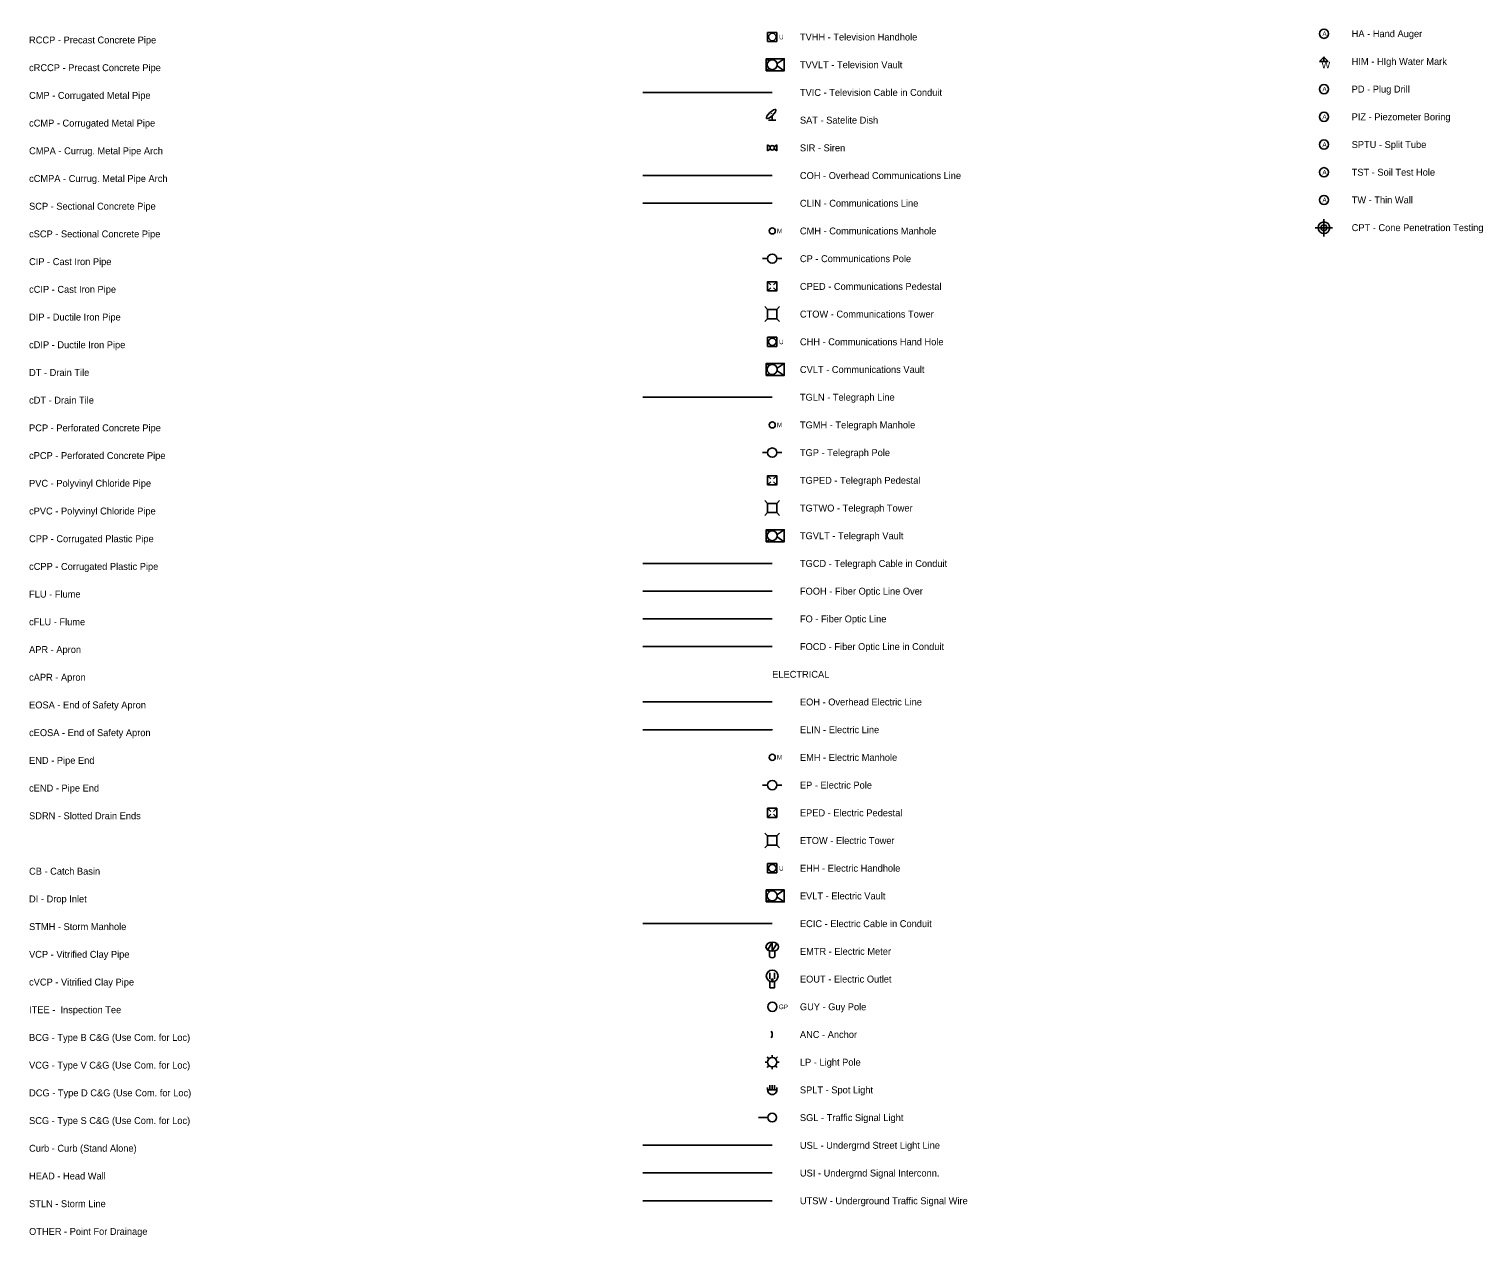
# Model space of a CAD drawing. Extents: x 2147712 to 2176316, y 2125036 to 2131746.
# Drawn here: x 2165470 to 2167044, y 2127374 to 2128682 of the extents above; entities that cross this region are included whole.
import ezdxf

# ---------------------------------------------------------------- set-up
doc = ezdxf.new("R2010")
doc.units = 0
for name, color, linetype in [('COMM LIN INP', 7, 'Continuous'), ('COMM PT INP', 7, 'Continuous'), ('Default', 7, 'Continuous'), ('MANMD STRU INP', 7, 'Continuous'), ('PWR LIN INP', 7, 'Continuous'), ('PWR LIN OVHD INP', 7, 'Continuous'), ('PWR PT INP', 7, 'Continuous')]:
    doc.layers.add(name, color=color, linetype=linetype)

msp = doc.modelspace()

# ---------------------------------------------------------------- linework, layer by layer
at = {"layer": 'COMM LIN INP'}
for p, q in [((2166134.5, 2128613.1), (2166274.5, 2128613.1)), ((2166134.5, 2128523.1), (2166274.5, 2128523.1)), ((2166134.5, 2128493.1), (2166274.5, 2128493.1)), ((2166134.5, 2128283.1), (2166274.5, 2128283.1)), ((2166134.5, 2128103.1), (2166274.5, 2128103.1)), ((2166134.5, 2128073.1), (2166274.5, 2128073.1)), ((2166134.5, 2128043.1), (2166274.5, 2128043.1)), ((2166134.5, 2128013.1), (2166274.5, 2128013.1))]:
    msp.add_line(p, q, dxfattribs=at)
at = {"layer": 'COMM PT INP'}
for p, q in [((2166274.5, 2128673.1), (2166274.5, 2128673.1)), ((2166268, 2128649.6), (2166271.3, 2128647.4)), ((2166287.5, 2128649.6), (2166279.7, 2128644.4)), ((2166271.3, 2128638.8), (2166268, 2128636.6)), ((2166279.7, 2128641.8), (2166287.5, 2128636.6)), ((2166270.6, 2128583.1), (2166278.4, 2128583.1)), ((2166273.9, 2128590), (2166273.3, 2128590.6)), ((2166274.5, 2128583.1), (2166274.5, 2128587.9)), ((2166269.5, 2128556.3), (2166269.5, 2128549.9)), ((2166272.5, 2128554.2), (2166269.5, 2128556.3)), ((2166272.5, 2128552), (2166269.5, 2128549.9)), ((2166276.5, 2128554.2), (2166279.5, 2128556.3)), ((2166276.5, 2128552), (2166279.5, 2128549.9)), ((2166279.5, 2128556.3), (2166279.5, 2128549.9)), ((2166269.5, 2128433.1), (2166263.9, 2128433.1)), ((2166279.5, 2128433.1), (2166285.1, 2128433.1)), ((2166269.5, 2128408.1), (2166273, 2128404.6)), ((2166276, 2128404.6), (2166279.5, 2128408.1)), ((2166269.5, 2128398.1), (2166273, 2128401.6)), ((2166274.5, 2128403.1), (2166274.5, 2128403.1)), ((2166276, 2128401.6), (2166279.5, 2128398.1)), ((2166266.5, 2128381.1), (2166269.5, 2128378.1)), ((2166282.5, 2128381.1), (2166279.5, 2128378.1)), ((2166269.5, 2128368.1), (2166266.5, 2128365.1)), ((2166274.5, 2128373.1), (2166274.5, 2128373.1)), ((2166279.5, 2128368.1), (2166282.5, 2128365.1)), ((2166274.5, 2128343.1), (2166274.5, 2128343.1)), ((2166268, 2128319.6), (2166271.3, 2128317.4)), ((2166287.5, 2128319.6), (2166279.7, 2128314.4)), ((2166271.3, 2128308.8), (2166268, 2128306.6)), ((2166279.7, 2128311.8), (2166287.5, 2128306.6)), ((2166269.5, 2128223.1), (2166263.9, 2128223.1)), ((2166279.5, 2128223.1), (2166285.1, 2128223.1)), ((2166269.5, 2128198.1), (2166273, 2128194.6)), ((2166269.5, 2128188.1), (2166273, 2128191.6)), ((2166274.5, 2128193.1), (2166274.5, 2128193.1)), ((2166276, 2128194.6), (2166279.5, 2128198.1)), ((2166276, 2128191.6), (2166279.5, 2128188.1)), ((2166266.5, 2128171.1), (2166269.5, 2128168.1)), ((2166269.5, 2128158.1), (2166266.5, 2128155.1)), ((2166274.5, 2128163.1), (2166274.5, 2128163.1)), ((2166282.5, 2128171.1), (2166279.5, 2128168.1)), ((2166279.5, 2128158.1), (2166282.5, 2128155.1)), ((2166268, 2128139.6), (2166271.3, 2128137.4)), ((2166271.3, 2128128.8), (2166268, 2128126.6)), ((2166287.5, 2128139.6), (2166279.7, 2128134.4)), ((2166279.7, 2128131.8), (2166287.5, 2128126.6))]:
    msp.add_line(p, q, dxfattribs=at)
for points in [[(2166269.5, 2128678.1), (2166279.5, 2128678.1)], [(2166269.5, 2128678.1), (2166269.5, 2128668.1)], [(2166279.5, 2128678.1), (2166279.5, 2128668.1)], [(2166269.5, 2128668.1), (2166279.5, 2128668.1)], [(2166269.5, 2128348.1), (2166279.5, 2128348.1)], [(2166269.5, 2128348.1), (2166269.5, 2128338.1)], [(2166279.5, 2128348.1), (2166279.5, 2128338.1)], [(2166269.5, 2128338.1), (2166279.5, 2128338.1)]]:
    msp.add_lwpolyline(points, dxfattribs=at)
for points in [[(2166268, 2128636.6), (2166287.5, 2128636.6), (2166287.5, 2128649.6), (2166268, 2128649.6)], [(2166269.5, 2128398.1), (2166279.5, 2128398.1), (2166279.5, 2128408.1), (2166269.5, 2128408.1)], [(2166269.5, 2128368.1), (2166279.5, 2128368.1), (2166279.5, 2128378.1), (2166269.5, 2128378.1)], [(2166268, 2128306.6), (2166287.5, 2128306.6), (2166287.5, 2128319.6), (2166268, 2128319.6)], [(2166269.5, 2128188.1), (2166279.5, 2128188.1), (2166279.5, 2128198.1), (2166269.5, 2128198.1)], [(2166269.5, 2128158.1), (2166279.5, 2128158.1), (2166279.5, 2128168.1), (2166269.5, 2128168.1)], [(2166268, 2128126.6), (2166287.5, 2128126.6), (2166287.5, 2128139.6), (2166268, 2128139.6)]]:
    msp.add_lwpolyline(points, close=True, dxfattribs=at)
for centre, radius in [((2166274.6, 2128673.1), 4.01), ((2166274.5, 2128643.1), 5.4), ((2166274.5, 2128553.1), 2.38), ((2166274.5, 2128463.1), 3.31), ((2166274.5, 2128433.1), 5), ((2166274.6, 2128343.1), 4.01), ((2166274.5, 2128313.1), 5.4), ((2166274.5, 2128253.1), 3.31), ((2166274.5, 2128223.1), 5), ((2166274.5, 2128133.1), 5.4)]:
    msp.add_circle(centre, radius, dxfattribs=at)
msp.add_ellipse((2166273.4, 2128589.7), major_axis=(-4.99, -4.74), ratio=0.30554, dxfattribs=at)
at = {"layer": 'Default'}
for p, q in [((2166871.9, 2128651.3), (2166876.6, 2128646.6)), ((2166871.9, 2128646.6), (2166876.6, 2128646.6)), ((2166871.9, 2128466.6), (2166871.9, 2128476)), ((2166871.9, 2128472.8), (2166871.9, 2128469.7)), ((2166871.9, 2128466.6), (2166862.5, 2128466.6)), ((2166868.8, 2128466.6), (2166865.7, 2128466.6)), ((2166871.9, 2128466.6), (2166871.9, 2128457.2)), ((2166871.9, 2128466.6), (2166881.3, 2128466.6)), ((2166871.9, 2128460.4), (2166871.9, 2128463.5)), ((2166875, 2128466.6), (2166878.1, 2128466.6))]:
    msp.add_line(p, q, dxfattribs=at)
msp.add_lwpolyline([(2166867.2, 2128646.6), (2166871.9, 2128651.3), (2166871.9, 2128646.6)], close=True, dxfattribs=at)
for points in [[(2166868.8, 2128466.6), (2166871.9, 2128466.6), (2166871.9, 2128469.7)], [(2166875, 2128466.6), (2166871.9, 2128466.6), (2166871.9, 2128463.5)]]:
    msp.add_lwpolyline(points, dxfattribs=at)
for centre, radius in [((2166871.9, 2128676.6), 5), ((2166871.9, 2128616.6), 5), ((2166871.9, 2128586.6), 5), ((2166871.9, 2128556.6), 5), ((2166871.9, 2128526.6), 5), ((2166871.9, 2128496.6), 5), ((2166871.9, 2128466.6), 6.25)]:
    msp.add_circle(centre, radius, dxfattribs=at)
for radius, start, end in [(6.25, 0, 90), (6.25, 180, 270), (3.12, 90, 180), (3.12, 180, 270), (3.12, 0, 90), (3.12, 270, 360)]:
    msp.add_arc((2166871.9, 2128466.6), radius, start, end, dxfattribs=at)
at = {"layer": 'MANMD STRU INP'}
msp.add_line((2166269.7, 2127503.1), (2166259.5, 2127503.1), dxfattribs=at)
msp.add_circle((2166274.5, 2127503.1), 4.76, dxfattribs=at)
at = {"layer": 'PWR LIN INP'}
for p, q in [((2166134.5, 2127923.1), (2166274.5, 2127923.1)), ((2166134.5, 2127713.1), (2166274.5, 2127713.1)), ((2166134.5, 2127473.1), (2166274.5, 2127473.1)), ((2166134.5, 2127443.1), (2166274.5, 2127443.1)), ((2166134.5, 2127413.1), (2166274.5, 2127413.1))]:
    msp.add_line(p, q, dxfattribs=at)
at = {"layer": 'PWR LIN OVHD INP'}
msp.add_line((2166274.5, 2127953.1), (2166134.5, 2127953.1), dxfattribs=at)
at = {"layer": 'PWR PT INP'}
for p, q in [((2166274.4, 2127922.9), (2166274.6, 2127923.3)), ((2166274.4, 2127923.3), (2166274.6, 2127922.9)), ((2166269.5, 2127863.1), (2166263.9, 2127863.1)), ((2166279.5, 2127863.1), (2166285.1, 2127863.1)), ((2166269.5, 2127838.1), (2166273, 2127834.6)), ((2166269.5, 2127828.1), (2166273, 2127831.6)), ((2166274.5, 2127833.1), (2166274.5, 2127833.1)), ((2166276, 2127834.6), (2166279.5, 2127838.1)), ((2166276, 2127831.6), (2166279.5, 2127828.1)), ((2166266.5, 2127811.1), (2166269.5, 2127808.1)), ((2166282.5, 2127811.1), (2166279.5, 2127808.1)), ((2166269.5, 2127798.1), (2166266.5, 2127795.1)), ((2166274.5, 2127803.1), (2166274.5, 2127803.1)), ((2166279.5, 2127798.1), (2166282.5, 2127795.1)), ((2166274.5, 2127773.1), (2166274.5, 2127773.1)), ((2166268, 2127749.6), (2166271.3, 2127747.4)), ((2166287.5, 2127749.6), (2166279.7, 2127744.4)), ((2166271.3, 2127738.8), (2166268, 2127736.6)), ((2166279.7, 2127741.8), (2166287.5, 2127736.6)), ((2166269.7, 2127684.6), (2166274.5, 2127692.9)), ((2166271.5, 2127683.6), (2166271.5, 2127678)), ((2166274.5, 2127692.9), (2166274.5, 2127683.1)), ((2166274.5, 2127683.1), (2166279.4, 2127691.5)), ((2166277.5, 2127683.6), (2166277.5, 2127678)), ((2166272.1, 2127660), (2166272.1, 2127653.2)), ((2166276.9, 2127660), (2166276.9, 2127653.2)), ((2166272.1, 2127643.4), (2166272.1, 2127650.5)), ((2166272.1, 2127643.4), (2166276.9, 2127643.4)), ((2166276.9, 2127643.4), (2166276.9, 2127650.5)), ((2166266.9, 2127563.1), (2166269.5, 2127563.1)), ((2166271, 2127566.6), (2166269, 2127568.7)), ((2166269, 2127557.5), (2166271, 2127559.6)), ((2166274.5, 2127568.1), (2166274.5, 2127570.7)), ((2166274.5, 2127563.1), (2166274.5, 2127563.1)), ((2166274.5, 2127555.5), (2166274.5, 2127558.1)), ((2166278, 2127566.6), (2166280.1, 2127568.7)), ((2166279.6, 2127557.5), (2166278, 2127559.6)), ((2166279.6, 2127563.1), (2166282.1, 2127563.1)), ((2166269.5, 2127533.1), (2166269.5, 2127535.6)), ((2166269.5, 2127533.1), (2166279.5, 2127533.1)), ((2166272, 2127533.1), (2166272, 2127538.1)), ((2166274.5, 2127533.1), (2166274.5, 2127538.1)), ((2166274.5, 2127533.1), (2166274.5, 2127533.1)), ((2166277, 2127533.1), (2166277, 2127538.1)), ((2166279.5, 2127533.1), (2166279.5, 2127535.6))]:
    msp.add_line(p, q, dxfattribs=at)
for points in [[(2166269.5, 2127828.1), (2166279.5, 2127828.1), (2166279.5, 2127838.1), (2166269.5, 2127838.1)], [(2166269.5, 2127798.1), (2166279.5, 2127798.1), (2166279.5, 2127808.1), (2166269.5, 2127808.1)], [(2166268, 2127736.6), (2166287.5, 2127736.6), (2166287.5, 2127749.6), (2166268, 2127749.6)]]:
    msp.add_lwpolyline(points, close=True, dxfattribs=at)
for points in [[(2166269.5, 2127778.1), (2166279.5, 2127778.1)], [(2166269.5, 2127778.1), (2166269.5, 2127768.1)], [(2166279.5, 2127778.1), (2166279.5, 2127768.1)], [(2166269.5, 2127768.1), (2166279.5, 2127768.1)]]:
    msp.add_lwpolyline(points, dxfattribs=at)
for centre, radius in [((2166274.5, 2127893.1), 3.31), ((2166274.5, 2127863.1), 5), ((2166274.6, 2127773.1), 4.01), ((2166274.5, 2127743.1), 5.4), ((2166274.5, 2127656.4), 6.39), ((2166274.5, 2127652.2), 0.9), ((2166274.6, 2127623.1), 5), ((2166274.5, 2127563.1), 5)]:
    msp.add_circle(centre, radius, dxfattribs=at)
for centre, radius, start, end in [((2166268.3, 2127593.1), 6.29, 324.6924, 35.1858), ((2166274.5, 2127533.1), 5, 179.996, 0.004)]:
    msp.add_arc(centre, radius, start, end, dxfattribs=at)
msp.add_ellipse((2166274.5, 2127688), major_axis=(-6.9, 0), ratio=0.710145, dxfattribs=at)
msp.add_ellipse((2166274.5, 2127678), major_axis=(-3, 0), ratio=0.602742, start_param=0, end_param=3.141593, dxfattribs=at)

# ---------------------------------------------------------------- texts
at = {"layer": 'COMM PT INP'}
for s, p in [('U', (2166281.9, 2128670.5)), ('M', (2166279.6, 2128460.6)), ('U', (2166281.9, 2128340.5)), ('M', (2166279.6, 2128250.6))]:
    msp.add_text(s, height=5, dxfattribs=at).set_placement(p)
at = {"layer": 'Default'}
for s, height, p in [('TVHH - Television Handhole', 7.5, (2166304.5, 2128669.3)), ('A', 5, (2166870.2, 2128674.1)), ('HA - Hand Auger', 7.5, (2166901.9, 2128672.9)), ('RCCP - Precast Concrete Pipe', 7.5, (2165469.9, 2128666.1)), ('cRCCP - Precast Concrete Pipe', 7.5, (2165469.9, 2128636.1)), ('TVVLT - Television Vault', 7.5, (2166304.5, 2128639.3)), ('W', 7.5, (2166869.2, 2128639)), ('HIM - HIgh Water Mark', 7.5, (2166901.9, 2128642.9)), ('CMP - Corrugated Metal Pipe', 7.5, (2165469.9, 2128606.1)), ('TVIC - Television Cable in Conduit', 7.5, (2166304.5, 2128609.3)), ('A', 5, (2166870.2, 2128614.1)), ('PD - Plug Drill', 7.5, (2166901.9, 2128612.9)), ('cCMP - Corrugated Metal Pipe', 7.5, (2165469.9, 2128576.1)), ('SAT - Satelite Dish', 7.5, (2166304.5, 2128579.3)), ('A', 5, (2166870.2, 2128584.1)), ('PIZ - Piezometer Boring', 7.5, (2166901.9, 2128582.9)), ('CMPA - Currug. Metal Pipe Arch', 7.5, (2165469.9, 2128546.1)), ('SIR - Siren', 7.5, (2166304.5, 2128549.3)), ('A', 5, (2166870.2, 2128554.1)), ('SPTU - Split Tube', 7.5, (2166901.9, 2128552.9)), ('cCMPA - Currug. Metal Pipe Arch', 7.5, (2165469.9, 2128516.1)), ('COH - Overhead Communications Line', 7.5, (2166304.5, 2128519.3)), ('A', 5, (2166870.2, 2128524.1)), ('TST - Soil Test Hole', 7.5, (2166901.9, 2128522.9)), ('SCP - Sectional Concrete Pipe', 7.5, (2165469.9, 2128486.1)), ('CLIN - Communications Line', 7.5, (2166304.5, 2128489.3)), ('A', 5, (2166870.2, 2128494.1)), ('TW - Thin Wall', 7.5, (2166901.9, 2128492.9)), ('CPT - Cone Penetration Testing', 7.5, (2166901.9, 2128462.9)), ('cSCP - Sectional Concrete Pipe', 7.5, (2165469.9, 2128456.1)), ('CMH - Communications Manhole', 7.5, (2166304.5, 2128459.3)), ('CIP - Cast Iron Pipe', 7.5, (2165469.9, 2128426.1)), ('CP - Communications Pole', 7.5, (2166304.5, 2128429.3)), ('cCIP - Cast Iron Pipe', 7.5, (2165469.9, 2128396.1)), ('CPED - Communications Pedestal', 7.5, (2166304.5, 2128399.3)), ('CTOW - Communications Tower', 7.5, (2166304.5, 2128369.3)), ('DIP - Ductile Iron Pipe', 7.5, (2165469.9, 2128366.1)), ('CHH - Communications Hand Hole', 7.5, (2166304.5, 2128339.3)), ('cDIP - Ductile Iron Pipe', 7.5, (2165469.9, 2128336.1)), ('DT - Drain Tile', 7.5, (2165469.9, 2128306.1)), ('CVLT - Communications Vault', 7.5, (2166304.5, 2128309.3)), ('cDT - Drain Tile', 7.5, (2165469.9, 2128276.1)), ('TGLN - Telegraph Line', 7.5, (2166304.5, 2128279.3)), ('PCP - Perforated Concrete Pipe', 7.5, (2165469.9, 2128246.1)), ('TGMH - Telegraph Manhole', 7.5, (2166304.5, 2128249.3)), ('cPCP - Perforated Concrete Pipe', 7.5, (2165469.9, 2128216.1)), ('TGP - Telegraph Pole', 7.5, (2166304.5, 2128219.3)), ('PVC - Polyvinyl Chloride Pipe', 7.5, (2165469.9, 2128186.1)), ('TGPED - Telegraph Pedestal', 7.5, (2166304.5, 2128189.3)), ('cPVC - Polyvinyl Chloride Pipe', 7.5, (2165469.9, 2128156.1)), ('TGTWO - Telegraph Tower', 7.5, (2166304.5, 2128159.3)), ('CPP - Corrugated Plastic Pipe', 7.5, (2165469.9, 2128126.1)), ('TGVLT - Telegraph Vault', 7.5, (2166304.5, 2128129.3)), ('cCPP - Corrugated Plastic Pipe', 7.5, (2165469.9, 2128096.1)), ('TGCD - Telegraph Cable in Conduit', 7.5, (2166304.5, 2128099.3)), ('FOOH - Fiber Optic Line Over', 7.5, (2166304.5, 2128069.3)), ('FLU - Flume', 7.5, (2165469.9, 2128066.1)), ('FO - Fiber Optic Line ', 7.5, (2166304.5, 2128039.3)), ('cFLU - Flume', 7.5, (2165469.9, 2128036.1)), ('FOCD - Fiber Optic Line in Conduit', 7.5, (2166304.5, 2128009.3)), ('APR - Apron', 7.5, (2165469.9, 2128006.1)), ('cAPR - Apron', 7.5, (2165469.9, 2127976.1)), ('ELECTRICAL', 7.5, (2166274.5, 2127979.3)), ('EOSA - End of Safety Apron', 7.5, (2165469.9, 2127946.1)), ('EOH - Overhead Electric Line', 7.5, (2166304.5, 2127949.3)), ('cEOSA - End of Safety Apron', 7.5, (2165469.9, 2127916.1)), ('ELIN - Electric Line', 7.5, (2166304.5, 2127919.3)), ('END - Pipe End', 7.5, (2165469.9, 2127886.1)), ('EMH - Electric Manhole', 7.5, (2166304.5, 2127889.3)), ('cEND - Pipe End', 7.5, (2165469.9, 2127856.1)), ('EP - Electric Pole', 7.5, (2166304.5, 2127859.3)), ('SDRN - Slotted Drain Ends', 7.5, (2165469.9, 2127826.1)), ('EPED - Electric Pedestal', 7.5, (2166304.5, 2127829.3)), ('ETOW - Electric Tower', 7.5, (2166304.5, 2127799.3)), ('CB - Catch Basin', 7.5, (2165469.9, 2127766.1)), ('EHH - Electric Handhole', 7.5, (2166304.5, 2127769.3)), ('EVLT - Electric Vault', 7.5, (2166304.5, 2127739.3)), ('DI - Drop Inlet', 7.5, (2165469.9, 2127736.1)), ('ECIC - Electric Cable in Conduit', 7.5, (2166304.5, 2127709.3)), ('STMH - Storm Manhole', 7.5, (2165469.9, 2127706.1)), ('VCP - Vitrified Clay Pipe', 7.5, (2165469.9, 2127676.1)), ('EMTR - Electric Meter', 7.5, (2166304.5, 2127679.3)), ('cVCP - Vitrified Clay Pipe', 7.5, (2165469.9, 2127646.1)), ('EOUT - Electric Outlet', 7.5, (2166304.5, 2127649.3)), ('ITEE -  Inspection Tee', 7.5, (2165469.9, 2127616.1)), ('GUY - Guy Pole', 7.5, (2166304.5, 2127619.3)), ('BCG - Type B C&G (Use Com. for Loc)', 7.5, (2165469.9, 2127586.1)), ('ANC - Anchor', 7.5, (2166304.5, 2127589.3)), ('VCG - Type V C&G (Use Com. for Loc)', 7.5, (2165469.9, 2127556.1)), ('LP - Light Pole', 7.5, (2166304.5, 2127559.3)), ('DCG - Type D C&G (Use Com. for Loc)', 7.5, (2165469.9, 2127526.1)), ('SPLT - Spot Light', 7.5, (2166304.5, 2127529.3)), ('SCG - Type S C&G (Use Com. for Loc)', 7.5, (2165469.9, 2127496.1)), ('SGL - Traffic Signal Light', 7.5, (2166304.5, 2127499.3)), ('Curb - Curb (Stand Alone)', 7.5, (2165469.9, 2127466.1)), ('USL - Undergrnd Street Light Line', 7.5, (2166304.5, 2127469.3)), ('USI - Undergrnd Signal Interconn.', 7.5, (2166304.5, 2127439.3)), ('HEAD - Head Wall', 7.5, (2165469.9, 2127436.1)), ('UTSW - Underground Traffic Signal Wire', 7.5, (2166304.5, 2127409.3)), ('STLN - Storm Line', 7.5, (2165469.9, 2127406.1)), ('OTHER - Point For Drainage', 7.5, (2165469.9, 2127376.1))]:
    msp.add_text(s, height=height, dxfattribs=at).set_placement(p)
at = {"layer": 'PWR PT INP'}
for s, p in [('M', (2166279.6, 2127890.6)), ('U', (2166281.9, 2127770.5)), ('GP', (2166281.6, 2127620.5))]:
    msp.add_text(s, height=5, dxfattribs=at).set_placement(p)

doc.saveas('drawing.dxf')
